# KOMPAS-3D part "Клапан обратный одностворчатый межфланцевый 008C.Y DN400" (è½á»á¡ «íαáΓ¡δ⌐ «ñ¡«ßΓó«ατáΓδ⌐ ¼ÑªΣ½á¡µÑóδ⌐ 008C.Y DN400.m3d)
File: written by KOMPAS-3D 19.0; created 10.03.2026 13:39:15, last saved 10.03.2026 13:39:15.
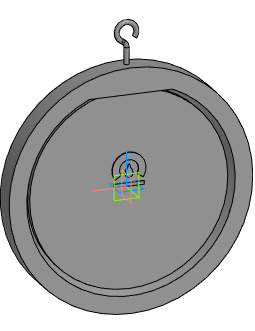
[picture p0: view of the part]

Document properties: Автор: Евгений; Полное имя файла: E:\Dendor\3D для проектировщиков\5.1 Тип 008C. Клапан обратный одностворчатый межфланцевый\stp_Клапан обратный одностворчатый межфланцевый 008C.Y\Клапан обратный одностворчатый межфланцевый 008C.Y DN400.m3d

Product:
- Part/product: Клапан обратный одностворчатый межфланцевый 008C.Y DN400

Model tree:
1. Операция без истории:1  (labels: Клапан обратный одностворчатый межфланцевый 008C.Y DN400)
